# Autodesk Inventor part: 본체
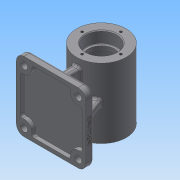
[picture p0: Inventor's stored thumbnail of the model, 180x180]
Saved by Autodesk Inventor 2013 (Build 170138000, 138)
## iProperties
Created: 2019-06
Part Number: 본체
Material: 일반
Document SubType Name: Modeling
Designer: Administrator
Density: 1 g/cm^3
Author: Administrator
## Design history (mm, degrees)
sketch "스케치1"
  geometry: C1 r 32 at (0, 0); 1 further point
  constraints: 1 centre point, 1 coincident
  dimensions: "d0" = 64 diameter of C1
extrude "돌출1" new body sketch "스케치1" stored distance "d1" = 90; taper "d2" = 0 deg
node "작업 평면1"
sketch "스케치2"
  geometry: L1 (0, 45)-(0, -45); L2 (32, 45)-(-32, 45) reference; L3 (-32, -45)-(32, -45) reference; L4 (0, 45)-(20, 45); L5 (20, 45)-(20, 30); L6 (20, 30)-(17, 30); L7 (17, 30)-(17, 24); L8 (17, 24)-(25, 24); L9 (25, 24)-(25, -24); L10 (25, -24)-(17, -24); L11 (17, -24)-(17, -30); L12 (17, -30)-(20, -30); L13 (20, -30)-(20, -45); L14 (0, -45)-(20, -45); 2 further points
  constraints: 24 end point, 6 perpendicular, 4 parallel, 3 midpoint, 2 point on line, 1 coincident, 1 vertical
  dimensions: "d4" = 40 diameter of L5 L1; "d6" = 40 diameter of L13 L1; "d7" = 15 distance between parallel lines of L2 L6; "d8" = 15 distance between parallel lines of L3 L12; "d9" = 50 diameter of L9 L1; "d10" = 34 diameter of L7 L1; "d11" = 34 diameter of L11 L1; "d12" = 48 distance between parallel lines of L10 L8; "d13" = 6 distance between parallel lines of L8 L6
revolve "회전1" sketch "스케치2" stored, may be unused: angle "d14" = 90 deg
fillet "모깎기1" dims "d15" = 0.6
fillet "모깎기2" dims "d16" = 0.6
fillet "모깎기3" dims "d17" = 3
fillet "모깎기4" dims "d18" = 3
chamfer "모따기1" distance "d19" = 1; stored, may be unused: second distance "d20" = 2, angle "d21" = 45 deg
chamfer "모따기2" distance "d22" = 1; stored, may be unused: second distance "d23" = 2, angle "d24" = 45 deg
sketch "스케치3"
  geometry: C1 r 32 at (0, 0) reference; 1 further point
  constraints: 1 vertical alignment
  dimensions: "d25" = 25 distance of point (0, 25) C1.centre
hole "구멍1" sketch "스케치3" at (0, 25) diameter "d26" = 3.242; stored, may be unused: countersink angle "d30" = 90 deg, drill point angle "d32" = 118 deg; dims "d27" = 7, "d28" = 4, "d29" = 2, "d31" = 9
node "작업 평면2"
sketch "스케치4"
  geometry: L1 (-45, 45)-(45, 45); L2 (45, 45)-(45, -45); L3 (45, -45)-(-45, -45); L4 (-45, -45)-(-45, 45); L5 (-45, 45)-(45, -45); L6 (45, 45)-(-45, -45); 3 further points
  constraints: 12 end point, 3 midpoint, 2 parallel, 1 coincident, 1 horizontal, 1 perpendicular
  dimensions: "d37" = 90 distance of L2.end L3.end; "d38" = 90 distance of L1.end L2.end
extrude "돌출2" join sketch "스케치4" distance "d39" = 10; taper "d40" = 0 deg
sketch "스케치5"
  geometry: L1 (-5, -35)-(5, -35); L2 (5, -35)-(5, 35); L3 (5, 35)-(-5, 35); L4 (-5, 35)-(-5, -35); L5 (-5, -35)-(5, 35); L6 (5, -35)-(-5, 35); 3 further points
  constraints: 12 end point, 3 midpoint, 2 parallel, 1 coincident, 1 horizontal, 1 perpendicular
  dimensions: "d41" = 10 distance of L3.end L2.end; "d42" = 70 distance of L2.end L1.end
extrude "돌출3" join sketch "스케치5" stored distance "d43" = 10; taper "d44" = 0 deg
node "작업 평면3"
sketch "스케치6"
  geometry: L1 (35, -55)-(27.126, -33.367); L2 (45, -55)-(-45, -55) reference; L3 (45, -65)-(45, -55) reference; 1 further point
  constraints: 2 end point, 1 point on line
  dimensions: "d46" = 10 distance from line of L3 L1.start; "d47" = 110 deg angle of L2 L1
feature "리브1" sketch "스케치6" dims "d48" = 1, "d49" = 10, "d50" = 0, "d51" = 0, "d52" = 1, "d53" = 1
fillet "모깎기5" dims "d54" = 10
fillet "모깎기6" dims "d55" = 10
fillet "모깎기7" dims "d56" = 3
fillet "모깎기8" dims "d57" = 3
fillet "모깎기9" dims "d58" = 3
fillet "모깎기10" dims "d59" = 3
sketch "스케치7"
  geometry: L1 (-40, 40)-(40, 40); L2 (40, 40)-(40, -40); L3 (40, -40)-(-40, -40); L4 (-40, -40)-(-40, 40); L5 (-40, 40)-(40, -40); L6 (40, 40)-(-40, -40); 3 further points
  constraints: 12 end point, 3 midpoint, 2 parallel, 1 coincident, 1 horizontal, 1 perpendicular
  dimensions: "d60" = 80 distance of L2.end L3.end; "d61" = 80 distance of L1.end L2.end
extrude "돌출4" cut sketch "스케치7" distance "d62" = 5; taper "d63" = 0 deg
sketch "스케치8"
  geometry: C1 r 10 at (-35, 35); A1 r 10 centre (-35, 35) between (-35, 45) and (-45, 35) reference; 1 further point
  constraints: 1 centre point, 1 concentric
  dimensions: "d64" = 20 diameter of C1
extrude "돌출5" join sketch "스케치8" distance "d65" = 5; taper "d66" = 0 deg
fillet "모깎기11" dims "d67" = 3
fillet "모깎기12" dims "d68" = 3
sketch "스케치9"
  geometry: L1 (-35, -45)-(35, -45) reference; L2 (-45, 35)-(-45, -35) reference; C1 r 4.5 at (-35, -35); 1 further point
  constraints: 1 centre point
  dimensions: "d69" = 9 diameter of C1; "d70" = 10 distance from line of L1 C1.centre; "d71" = 10 distance from line of L2 C1.centre
extrude "돌출6" cut sketch "스케치9" stored distance "d72" = 5; taper "d73" = 0 deg
node "작업 평면4"
sketch "스케치10"
  geometry: C1 r 5 at (0, 0); 1 further point
  constraints: 1 centre point, 1 coincident
  dimensions: "d75" = 10 diameter of C1
extrude "돌출7" join sketch "스케치10" stored distance "d76" = 5; taper "d77" = 0 deg
fillet "모깎기13" dims "d78" = 2
sketch "스케치11"
  geometry: C1 r 5 at (0, 0) reference; 1 further point
  constraints: 1 coincident
hole "구멍2" sketch "스케치11" at (0, 0) diameter "d79" = 4.917; stored, may be unused: countersink angle "d83" = 90 deg, drill point angle "d85" = 118 deg; dims "d80" = 7, "d81" = 4, "d82" = 2, "d84" = 10
sketch "스케치12"
  geometry: L1 (70, 0)-(0, 0) reference; L2 (-10, 7)-(-10, 0) reference; 2 further points
  constraints: 1 other
  dimensions: "d86" = 45 distance from line of point (35, 4) L2; "d87" = 4 distance from line of L1 point (35, 4)
feature "엠보싱1" sketch "스케치12" dims "d4" = 40, "d6" = 40, "d7" = 15, "d8" = 15, "d9" = 50, "d10" = 34, "d11" = 34, "d12" = 48, "d13" = 6, "d88" = 0.5, "d89" = 0
node "솔리드1"
pattern_circular "원형 패턴1" dims angle "d34" = 360 deg
mirror "대칭1"
mirror "대칭2"
mirror "대칭3"
mirror "대칭4"
mirror "대칭5"
mirror "대칭6"
other parameters: "d3" = 0, "d36" = -65, "d45" = 0, "d74" = 35
